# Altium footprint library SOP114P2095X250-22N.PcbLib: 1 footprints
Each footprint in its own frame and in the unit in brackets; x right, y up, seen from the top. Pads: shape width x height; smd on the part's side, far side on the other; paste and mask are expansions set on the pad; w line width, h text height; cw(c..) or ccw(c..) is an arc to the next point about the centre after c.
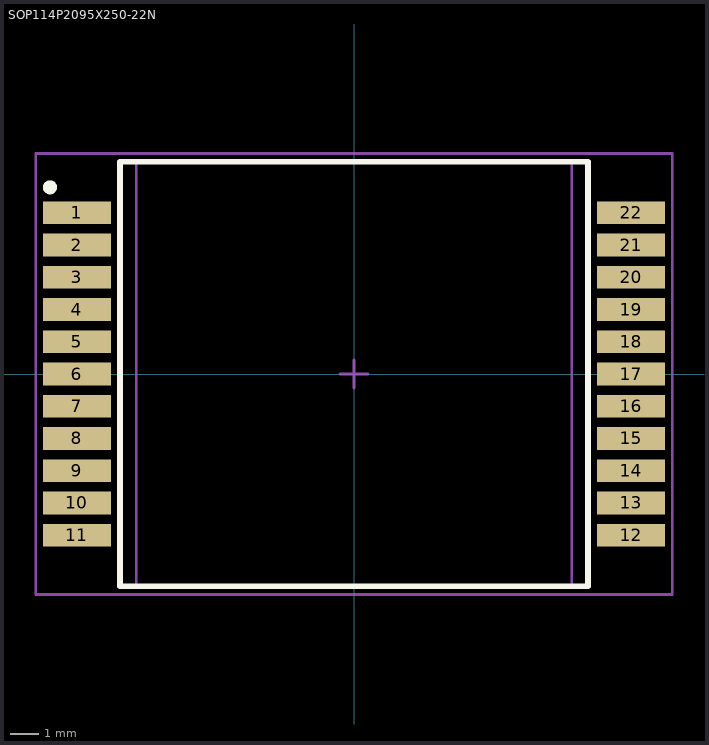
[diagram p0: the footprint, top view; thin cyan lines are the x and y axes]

## SOP114P2095X250-22N [mm] "SOP,1.14mm pitch;22 pin,15.40mm W X 15.00mm L X 2.50mm H body"
height 2.5
pads (22):
  rect 2.4x0.8 smd paste+0 mask+0: 1(-9.8,5.7) 2(-9.8,4.56) 3(-9.8,3.42) 4(-9.8,2.28) 5(-9.8,1.14) 6(-9.8,0) 7(-9.8,-1.14) 8(-9.8,-2.28) 9(-9.8,-3.42) 10(-9.8,-4.56) 11(-9.8,-5.7) 12(9.8,-5.7) 13(9.8,-4.56) 14(9.8,-3.42) 15(9.8,-2.28) 16(9.8,-1.14) 17(9.8,0) 18(9.8,1.14) 19(9.8,2.28) 20(9.8,3.42) 21(9.8,4.56) 22(9.8,5.7)
Top Overlay:
  circle w0.25: c-10.75,6.6 r0.125
  lines w0.2: -8.275,-7.5 -8.275,7.5 8.275,7.5 8.275,-7.5 -8.275,-7.5
M3 (ASY_Text_Top):
  text ".DESIGNATOR" at 0,0 h1.2
M13 (CMP_Body_OTL_Top):
  lines w0.1: -7.7,-7.5 7.7,-7.5 7.7,7.5 -7.7,7.5 -7.7,-7.5
M15 (CMP_Courtyard_Top):
  lines w0.1: -0.5,0 0.5,0 ; 0,-0.5 0,0.5 ; -11.25,-7.8 -11.25,7.8 11.25,7.8 11.25,-7.8 -11.25,-7.8
3D body "PG-HDSOP-22-1.stp": height 2.38, standoff 0, extent -10.48,-7.5 10.48,7.5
